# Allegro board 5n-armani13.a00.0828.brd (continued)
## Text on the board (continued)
Ref Des/Silkscreen Bottom: BOT | 2ND | 2'ND
TOP: list("[Spacing] TOP" "24.Shape to Route Keepin" "0 MIL [DEFAULT]" "0 MIL" "0.00 MIL" "DRC ERROR CLASS/TOP" "[Shape] Route Keepin/All ((-191.01 273.9) (8699.38 4792.96))" "[Top Shape] GND ((-190.82 3249.2) (202.99 3569.85))" list(-170.750000 3410.250000) nil)@@@list("iris_chen" "2017/08/22 17:12:43" nil "P16C000357-PC" "5n-armani13.a00")@@@list("anson_lee" "2017/08/24 14:21:02" nil "P172000029-PC" "5n-armani13.a00.0824") | list("[Physical] TOP" "234.Pad/Pad Direct Connect" "NOT_ALLOWED [(GND_20)]" "ALL_ALLOWED" "" "DRC ERROR CLASS/TOP" "[ThruPin] GND (<uTiL>cId2539<uTiL>.6) (-146.76 2401.5)" "[SmdPin] GND (<uTiL>cId2539<uTiL>.5) (-146.76 2401.5)" list(-146.760000 2401.500000) nil)@@@list("iris_chen" "2017/08/23 17:49:26" nil "P16C000357-PC" "5n-armani13.a00")@@@list("anson_lee" "2017/08/24 14:24:34" nil "P172000029-PC" "5n-armani13.a00.0824") | list("[Spacing] TOP" "15.Shape to Route Keepout" "0 MIL [DEFAULT]" "0 MIL" "0.00 MIL" "DRC ERROR CLASS/TOP" "[Shape] Route Keepout/Top ((-101.81 3966.17) (122.4 4195.17))" "[Top Shape] GND ((-191.0 273.91) (8699.37 4792.95))" list(-100.230000 3966.170000) nil)@@@list("iris_chen" "2017/08/22 17:12:55" nil "P16C000357-PC" "5n-armani13.a00")@@@list("anson_lee" "2017/08/24 14:20:44" nil "P172000029-PC" "5n-armani13.a00.0824") | list("[Spacing] TOP" "4.Shape to Route Keepin" "0 MIL [DEFAULT]" "0 MIL" "0.00 MIL" "DRC ERROR CLASS/TOP" "[Shape] Route Keepin/All ((-191.01 273.9) (8699.38 4792.96))" "[Top Shape] GND ((-91.81 3976.17) (117.19 4185.17))" list(-85.450000 3976.170000) nil)@@@list("iris_chen" "2017/08/22 17:12:50" nil "P16C000357-PC" "5n-armani13.a00")@@@list("anson_lee" "2017/08/24 14:08:54" nil "P172000029-PC" "5n-armani13.a00.0824") | list("[Spacing] TOP" "14.Shape to Route Keepin" "0 MIL [DEFAULT]" "0 MIL" "0.00 MIL" "DRC ERROR CLASS/TOP" "[Shape] Route Keepin/All ((-191.01 273.9) (8699.38 4792.96))" "[Top Shape] GND ((-191.0 273.91) (8699.37 4792.95))" list(-27.850000 3902.370000) nil)@@@list("iris_chen" "2017/08/22 17:12:54" nil "P16C000357-PC" "5n-armani13.a00")@@@list("anson_lee" "2017/08/24 14:20:43" nil "P172000029-PC" "5n-armani13.a00.0824") | list("[Spacing] TOP" "9.Shape to Route Keepout" "0 MIL [DEFAULT]" "0 MIL" "0.00 MIL" "DRC ERROR CLASS/TOP" "[Shape] Route Keepout/All ((-211.01 253.9) (8719.38 4812.96))" "[Top Shape] GND ((-24.57 3163.49) (207.43 3395.49))" list(-24.570000 3185.200000) nil)@@@list("iris_chen" "2017/08/22 17:12:52" nil "P16C000357-PC" "5n-armani13.a00")@@@list("anson_lee" "2017/08/24 14:08:59" nil "P172000029-PC" "5n-armani13.a00.0824") | list("[Spacing] TOP" "10.Shape to Route Keepout" "0 MIL [DEFAULT]" "0 MIL" "0.00 MIL" "DRC ERROR CLASS/TOP" "[Shape] Route Keepout/All ((-237.5 2495.83) (182.17 3240.31))" "[Top Shape] GND ((-24.57 3163.49) (207.43 3395.49))" list(-24.570000 3185.190000) nil)@@@list("iris_chen" "2017/08/22 17:12:52" nil "P16C000357-PC" "5n-armani13.a00")@@@list("anson_lee" "2017/08/24 14:09:00" nil "P172000029-PC" "5n-armani13.a00.0824") | list("[Spacing] TOP" "33.Thru Pin to Thru Pin" "5 MIL [(12)]" "4 MIL" "1.00 MIL" "DRC ERROR CLASS/TOP" "[ThruPin] TX2N_P1_C (<uTiL>cId4355<uTiL>.B3) (12.89 3746.02)" "[ThruPin] TX2P_P1_C (<uTiL>cId4355<uTiL>.B2) (12.89 3777.52)" list(12.890000 3759.770000) nil)@@@list("iris_chen" "2017/08/22 17:12:58" nil "P16C000357-PC" "5n-armani13.a00")@@@list("anson_lee" "2017/08/24 14:21:11" nil "P172000029-PC" "5n-armani13.a00.0824") | list("[Spacing] TOP" "17.Thru Pin to Thru Pin" "5 MIL [(12)]" "4 MIL" "1.00 MIL" "DRC ERROR CLASS/TOP" "[ThruPin] RX1N_P1 (<uTiL>cId4355<uTiL>.B10) (12.89 3612.16)" "[ThruPin] RX1P_P1 (<uTiL>cId4355<uTiL>.B11) (12.89 3580.66)" list(12.890000 3598.410000) nil)@@@list("iris_chen" "2017/08/22 17:12:47" nil "P16C000357-PC" "5n-armani13.a00")@@@list("anson_lee" "2017/08/24 14:20:53" nil "P172000029-PC" "5n-armani13.a00.0824") | list("[Spacing] TOP" "27.Shape to Route Keepin" "0 MIL [DEFAULT]" "0 MIL" "0.00 MIL" "DRC ERROR CLASS/TOP" "[Shape] Route Keepin/All ((-191.01 273.9) (8699.38 4792.96))" "[Top Shape] GND ((8.28 3791.73) (47.94 3896.23))" list(17.500000 3892.960000) nil)@@@list("iris_chen" "2017/08/22 17:12:53" nil "P16C000357-PC" "5n-armani13.a00")@@@list("anson_lee" "2017/08/24 14:21:05" nil "P172000029-PC" "5n-armani13.a00.0824") | list("[Spacing] TOP" "30.Thru Pin to Thru Pin" "5 MIL [(15)]" "4 MIL" "1.00 MIL" "DRC ERROR CLASS/TOP" "[ThruPin] DN2 (<uTiL>cId4355<uTiL>.B7) (48.32 3663.34)" "[ThruPin] DP2 (<uTiL>cId4355<uTiL>.B6) (48.32 3694.84)" list(48.320000 3677.090000) nil)@@@list("iris_chen" "2017/08/22 17:12:51" nil "P16C000357-PC" "5n-armani13.a00")@@@list("anson_lee" "2017/08/24 14:21:08" nil "P172000029-PC" "5n-armani13.a00.0824") | list("[Spacing] TOP" "12.Shape to Route Keepout" "0 MIL [DEFAULT]" "0 MIL" "0.00 MIL" "DRC ERROR CLASS/TOP" "[Shape] Route Keepout/Top ((-61.0 1381.68) (193.96 1653.68))" "[Top Shape] GND ((-82.35 352.64) (8095.0 1709.99))" list(183.940000 1648.680000) nil)@@@list("iris_chen" "2017/08/23 18:07:48" nil "P16C000357-PC" "5n-armani13.a00")@@@list("anson_lee" "2017/08/24 14:09:02" nil "P172000029-PC" "5n-armani13.a00.0824") | list("[Spacing] TOP" "1.Shape to Route Keepout" "0 MIL [DEFAULT]" "0 MIL" "0.00 MIL" "DRC ERROR CLASS/TOP" "[Shape] Route Keepout/Top ((-61.0 1381.68) (193.96 1653.68))" "[Top Shape] GND ((-68.02 1359.42) (183.94 1396.0))" list(183.940000 1381.680000) nil)@@@list("iris_chen" "2017/08/23 18:07:47" nil "P16C000357-PC" "5n-armani13.a00")@@@nil | list("[Spacing] TOP" "13.Shape to Route Keepout" "0 MIL [DEFAULT]" "0 MIL" "0.00 MIL" "DRC ERROR CLASS/TOP" "[Shape] Route Keepout/Top ((-61.0 1381.68) (193.96 1653.68))" "[Top Shape] GND ((-68.02 1364.0) (183.94 1396.0))" list(183.940000 1381.680000) nil)@@@list("iris_chen" "2017/08/24 08:51:33" nil "P16C000357-PC" "5n-armani13.a00")@@@list("anson_lee" "2017/08/24 14:09:04" nil "P172000029-PC" "5n-armani13.a00.0824") | list("[Spacing] TOP" "8.Shape to Route Keepin" "0 MIL [DEFAULT]" "0 MIL" "0.00 MIL" "DRC ERROR CLASS/TOP" "[Shape] Route Keepin/All ((-191.01 273.9) (8699.38 4792.96))" "[Top Shape] GND ((-24.57 3163.49) (207.43 3395.49))" list(188.890000 3163.490000) nil)@@@list("iris_chen" "2017/08/22 17:12:51" nil "P16C000357-PC" "5n-armani13.a00")@@@list("anson_lee" "2017/08/24 14:08:58" nil "P172000029-PC" "5n-armani13.a00.0824") | list("[Spacing] TOP" "18.Shape to Route Keepin" "0 MIL [DEFAULT]" "0 MIL" "0.00 MIL" "DRC ERROR CLASS/TOP" "[Shape] Route Keepin/All ((-191.01 273.9) (8699.38 4792.96))" "[Top Shape] GND ((-104.24 2487.0) (342.67 2651.0))" list(189.550000 2589.570000) nil)@@@list("iris_chen" "2017/08/22 17:12:38" nil "P16C000357-PC" "5n-armani13.a00")@@@list("anson_lee" "2017/08/24 14:20:55" nil "P172000029-PC" "5n-armani13.a00.0824") | list("[Physical] TOP" "210.Pad/Pad Direct Connect" "NOT_ALLOWED [85OHM(DP_4|4.3|4|5/4/5/200)]" "ALL_ALLOWED" "" "DRC ERROR CLASS/TOP" "[SmdPin] DP2 (<uTiL>cId4352<uTiL>.4) (300.0 3741.0)" "[SmdPin] DP2 (<uTiL>cId4354<uTiL>.3) (291.47 3739.83)" list(291.470000 3739.830000) nil)@@@list("iris_chen" "2017/08/22 17:19:08" nil "P16C000357-PC" "5n-armani13.a00")@@@list("anson_lee" "2017/08/24 14:24:14" nil "P172000029-PC" "5n-armani13.a00.0824") | list("[Physical] TOP" "206.Pad/Pad Direct Connect" "NOT_ALLOWED [85OHM(DP_4|4.3|4|5/4/5/200)]" "ALL_ALLOWED" "" "DRC ERROR CLASS/TOP" "[SmdPin] DN2 (<uTiL>cId4354<uTiL>.2) (291.47 3718.17)" "[SmdPin] DN2 (<uTiL>cId4352<uTiL>.2) (300.0 3717.0)" list(300.000000 3717.000000) nil)@@@list("iris_chen" "2017/08/22 17:18:53" nil "P16C000357-PC" "5n-armani13.a00")@@@list("anson_lee" "2017/08/24 14:24:11" nil "P172000029-PC" "5n-armani13.a00.0824") | list("[Physical] TOP" "220.Pad/Pad Direct Connect" "NOT_ALLOWED [85OHM(DP_4|4.3|4|5/4/5/200)]" "ALL_ALLOWED" "" "DRC ERROR CLASS/TOP" "[SmdPin] DP2_MUX (<uTiL>cId4354<uTiL>.4) (350.53 3739.83)" "[SmdPin] DP2_MUX (<uTiL>cId4352<uTiL>.3) (342.0 3741.0)" list(342.000000 3741.000000) nil)@@@list("iris_chen" "2017/08/22 17:18:50" nil "P16C000357-PC" "5n-armani13.a00")@@@list("anson_lee" "2017/08/24 14:24:22" nil "P172000029-PC" "5n-armani13.a00.0824") | list("[Physical] TOP" "211.Pad/Pad Direct Connect" "NOT_ALLOWED [85OHM(DP_4|4.3|4|5/4/5/200)]" "ALL_ALLOWED" "" "DRC ERROR CLASS/TOP" "[SmdPin] DN2_MUX (<uTiL>cId4352<uTiL>.1) (342.0 3717.0)" "[SmdPin] DN2_MUX (<uTiL>cId4354<uTiL>.1) (350.53 3718.17)" list(350.530000 3718.170000) nil)@@@list("iris_chen" "2017/08/22 17:19:07" nil "P16C000357-PC" "5n-armani13.a00")@@@list("anson_lee" "2017/08/24 14:24:15" nil "P172000029-PC" "5n-armani13.a00.0824") | list("[Physical] TOP" "204.Pad/Pad Direct Connect" "NOT_ALLOWED [100OHM(DP_#1/#2/5/200)]" "ALL_ALLOWED" "" "DRC ERROR CLASS/TOP" "[SmdPin] RX2N_P1 (<uTiL>cId5011<uTiL>.1) (452.0 3365.0)" "[SmdPin] RX2N_P1 (<uTiL>cId5017<uTiL>.1) (443.47 3364.83)" list(443.470000 3364.830000) nil)@@@list("iris_chen" "2017/08/22 17:19:06" nil "P16C000357-PC" "5n-armani13.a00")@@@list("anson_lee" "2017/08/24 14:24:10" nil "P172000029-PC" "5n-armani13.a00.0824") | list("[Physical] TOP" "208.Pad/Pad Direct Connect" "NOT_ALLOWED [100OHM(DP_#1/#2/5/200)]" "ALL_ALLOWED" "" "DRC ERROR CLASS/TOP" "[SmdPin] RX2P_P1 (<uTiL>cId5017<uTiL>.4) (443.47 3343.17)" "[SmdPin] RX2P_P1 (<uTiL>cId5011<uTiL>.3) (452.0 3341.0)" list(452.000000 3341.000000) nil)@@@list("iris_chen" "2017/08/22 17:18:58" nil "P16C000357-PC" "5n-armani13.a00")@@@list("anson_lee" "2017/08/24 14:24:13" nil "P172000029-PC" "5n-armani13.a00.0824") | list("[Physical] TOP" "245.Pad/Pad Direct Connect" "NOT_ALLOWED [100OHM(DP_#1/#2/5/200)]" "ALL_ALLOWED" "" "DRC ERROR CLASS/TOP" "[SmdPin] RX1P_P1 (<uTiL>cId5012<uTiL>.1) (470.0 3631.0)" "[SmdPin] RX1P_P1 (<uTiL>cId5018<uTiL>.1) (461.47 3629.83)" list(461.470000 3629.830000) nil)@@@list("iris_chen" "2017/08/22 17:18:57" nil "P16C000357-PC" "5n-armani13.a00")@@@list("anson_lee" "2017/08/24 14:24:41" nil "P172000029-PC" "5n-armani13.a00.0824") | list("[Physical] TOP" "221.Pad/Pad Direct Connect" "NOT_ALLOWED [100OHM(DP_#1/#2/5/200)]" "ALL_ALLOWED" "" "DRC ERROR CLASS/TOP" "[SmdPin] RX1N_P1 (<uTiL>cId5018<uTiL>.4) (461.47 3608.17)" "[SmdPin] RX1N_P1 (<uTiL>cId5012<uTiL>.3) (470.0 3607.0)" list(470.000000 3607.000000) nil)@@@list("iris_chen" "2017/08/22 17:19:03" nil "P16C000357-PC" "5n-armani13.a00")@@@list("anson_lee" "2017/08/24 14:24:23" nil "P172000029-PC" "5n-armani13.a00.0824") | list("[Physical] TOP" "222.Pad/Pad Direct Connect" "NOT_ALLOWED [100OHM(DP_#1/#2/5/200)]" "ALL_ALLOWED" "" "DRC ERROR CLASS/TOP" "[SmdPin] TX1P_P1 (<uTiL>cId5010<uTiL>.1) (488.0 3547.0)" "[SmdPin] TX1P_P1 (<uTiL>cId5016<uTiL>.1) (479.47 3545.83)" list(479.470000 3545.830000) nil)@@@list("iris_chen" "2017/08/22 17:18:52" nil "P16C000357-PC" "5n-armani13.a00")@@@list("anson_lee" "2017/08/24 14:24:24" nil "P172000029-PC" "5n-armani13.a00.0824") | list("[Physical] TOP" "241.Pad/Pad Direct Connect" "NOT_ALLOWED [100OHM(DP_#1/#2/5/200)]" "ALL_ALLOWED" "" "DRC ERROR CLASS/TOP" "[SmdPin] TX1N_P1 (<uTiL>cId5010<uTiL>.3) (488.0 3523.0)" "[SmdPin] TX1N_P1 (<uTiL>cId5016<uTiL>.4) (479.47 3524.17)" list(479.470000 3524.170000) nil)@@@list("iris_chen" "2017/08/22 17:19:04" nil "P16C000357-PC" "5n-armani13.a00")@@@list("anson_lee" "2017/08/24 14:24:39" nil "P172000029-PC" "5n-armani13.a00.0824") | list("[Physical] TOP" "242.Pad/Pad Direct Connect" "NOT_ALLOWED [100OHM(DP_#1/#2/5/200)]" "ALL_ALLOWED" "" "DRC ERROR CLASS/TOP" "[SmdPin] RX2N_P1_MUX (<uTiL>cId5017<uTiL>.2) (502.53 3364.83)" "[SmdPin] RX2N_P1_MUX (<uTiL>cId5011<uTiL>.2) (494.0 3365.0)" list(494.000000 3365.000000) nil)@@@list("iris_chen" "2017/08/22 17:19:06" nil "P16C000357-PC" "5n-armani13.a00")@@@list("anson_lee" "2017/08/24 14:24:39" nil "P172000029-PC" "5n-armani13.a00.0824") | list("[Physical] TOP" "219.Pad/Pad Direct Connect" "NOT_ALLOWED [100OHM(DP_#1/#2/5/200)]" "ALL_ALLOWED" "" "DRC ERROR CLASS/TOP" "[SmdPin] RX2P_P1_MUX (<uTiL>cId5011<uTiL>.4) (494.0 3341.0)" "[SmdPin] RX2P_P1_MUX (<uTiL>cId5017<uTiL>.3) (502.53 3343.17)" list(502.530000 3343.170000) nil)@@@list("iris_chen" "2017/08/22 17:18:52" nil "P16C000357-PC" "5n-armani13.a00")@@@list("anson_lee" "2017/08/24 14:24:21" nil "P172000029-PC" "5n-armani13.a00.0824") | list("[Physical] TOP" "217.Pad/Pad Direct Connect" "NOT_ALLOWED [100OHM(DP_#1/#2/5/200)]" "ALL_ALLOWED" "" "DRC ERROR CLASS/TOP" "[SmdPin] RX1P_P1_MUX (<uTiL>cId5012<uTiL>.2) (512.0 3631.0)" "[SmdPin] RX1P_P1_MUX (<uTiL>cId5018<uTiL>.2) (520.53 3629.83)" list(520.530000 3629.830000) nil)@@@list("iris_chen" "2017/08/22 17:19:01" nil "P16C000357-PC" "5n-armani13.a00")@@@list("anson_lee" "2017/08/24 14:24:20" nil "P172000029-PC" "5n-armani13.a00.0824") | list("[Physical] TOP" "240.Pad/Pad Direct Connect" "NOT_ALLOWED [100OHM(DP_#1/#2/5/200)]" "ALL_ALLOWED" "" "DRC ERROR CLASS/TOP" "[SmdPin] RX1N_P1_MUX (<uTiL>cId5012<uTiL>.4) (512.0 3607.0)" "[SmdPin] RX1N_P1_MUX (<uTiL>cId5018<uTiL>.3) (520.53 3608.17)" list(520.530000 3608.170000) nil)@@@list("iris_chen" "2017/08/22 17:18:53" nil "P16C000357-PC" "5n-armani13.a00")@@@list("anson_lee" "2017/08/24 14:24:38" nil "P172000029-PC" "5n-armani13.a00.0824") | list("[Physical] TOP" "207.Pad/Pad Direct Connect" "NOT_ALLOWED [100OHM(DP_#1/#2/5/200)]" "ALL_ALLOWED" "" "DRC ERROR CLASS/TOP" "[SmdPin] TX1N_P1_MUX (<uTiL>cId5016<uTiL>.3) (538.53 3524.17)" "[SmdPin] TX1N_P1_MUX (<uTiL>cId5010<uTiL>.4) (530.0 3523.0)" list(530.000000 3523.000000) nil)@@@list("iris_chen" "2017/08/22 17:19:10" nil "P16C000357-PC" "5n-armani13.a00")@@@list("anson_lee" "2017/08/24 14:24:12" nil "P172000029-PC" "5n-armani13.a00.0824") | list("[Physical] TOP" "218.Pad/Pad Direct Connect" "NOT_ALLOWED [100OHM(DP_#1/#2/5/200)]" "ALL_ALLOWED" "" "DRC ERROR CLASS/TOP" "[SmdPin] TX1P_P1_MUX (<uTiL>cId5010<uTiL>.2) (530.0 3547.0)" "[SmdPin] TX1P_P1_MUX (<uTiL>cId5016<uTiL>.2) (538.53 3545.83)" list(538.530000 3545.830000) nil)@@@list("iris_chen" "2017/08/22 17:19:10" nil "P16C000357-PC" "5n-armani13.a00")@@@list("anson_lee" "2017/08/24 14:24:20" nil "P172000029-PC" "5n-armani13.a00.0824") | list("[Physical] TOP" "216.Pad/Pad Direct Connect" "NOT_ALLOWED [100OHM(DP_#1/#2/5/200)]" "ALL_ALLOWED" "" "DRC ERROR CLASS/TOP" "[SmdPin] TX2P_P1 (<uTiL>cId5009<uTiL>.3) (626.0 3449.0)" "[SmdPin] TX2P_P1 (<uTiL>cId5015<uTiL>.4) (617.47 3450.17)" list(617.470000 3450.170000) nil)@@@list("iris_chen" "2017/08/22 17:19:05" nil "P16C000357-PC" "5n-armani13.a00")@@@list("anson_lee" "2017/08/24 14:24:19" nil "P172000029-PC" "5n-armani13.a00.0824") | list("[Physical] TOP" "243.Pad/Pad Direct Connect" "NOT_ALLOWED [100OHM(DP_#1/#2/5/200)]" "ALL_ALLOWED" "" "DRC ERROR CLASS/TOP" "[SmdPin] TX2N_P1 (<uTiL>cId5015<uTiL>.1) (617.47 3471.83)" "[SmdPin] TX2N_P1 (<uTiL>cId5009<uTiL>.1) (626.0 3473.0)" list(626.000000 3473.000000) nil)@@@list("iris_chen" "2017/08/22 17:19:04" nil "P16C000357-PC" "5n-armani13.a00")@@@list("anson_lee" "2017/08/24 14:24:40" nil "P172000029-PC" "5n-armani13.a00.0824") | list("[Physical] TOP" "223.Pad/Pad Direct Connect" "NOT_ALLOWED [100OHM(DP_#1/#2/5/200)]" "ALL_ALLOWED" "" "DRC ERROR CLASS/TOP" "[SmdPin] TX2N_P1_MUX (<uTiL>cId5009<uTiL>.2) (668.0 3473.0)" "[SmdPin] TX2N_P1_MUX (<uTiL>cId5015<uTiL>.2) (676.53 3471.83)" list(676.530000 3471.830000) nil)@@@list("iris_chen" "2017/08/22 17:19:08" nil "P16C000357-PC" "5n-armani13.a00")@@@list("anson_lee" "2017/08/24 14:24:25" nil "P172000029-PC" "5n-armani13.a00.0824") | list("[Physical] TOP" "205.Pad/Pad Direct Connect" "NOT_ALLOWED [100OHM(DP_#1/#2/5/200)]" "ALL_ALLOWED" "" "DRC ERROR CLASS/TOP" "[SmdPin] TX2P_P1_MUX (<uTiL>cId5009<uTiL>.4) (668.0 3449.0)" "[SmdPin] TX2P_P1_MUX (<uTiL>cId5015<uTiL>.3) (676.53 3450.17)" list(676.530000 3450.170000) nil)@@@list("iris_chen" "2017/08/22 17:18:59" nil "P16C000357-PC" "5n-armani13.a00")@@@list("anson_lee" "2017/08/24 14:24:10" nil "P172000029-PC" "5n-armani13.a00.0824") | list("[Physical] TOP" "202.DiffPair Min Gap" "11.99 MIL [100OHM(DP_#1/#2/5/200)]" "10.19 MIL" "1.80 MIL" "DRC ERROR CLASS/TOP" "[Line] TX2P_P1_MUX ((750.27 3468.26) (770.0 3472.26))" "[Line] TX2N_P1_MUX ((715.37 3479.0) (744.99 3483.0))" list(752.270000 3470.260000) nil)@@@list("iris_chen" "2017/08/22 17:18:58" nil "P16C000357-PC" "5n-armani13.a00")@@@list("anson_lee" "2017/08/24 14:24:08" nil "P172000029-PC" "5n-armani13.a00.0824") | list("[Physical] TOP" "203.DiffPair Min Gap" "11.99 MIL [100OHM(DP_#1/#2/5/200)]" "10.19 MIL" "1.80 MIL" "DRC ERROR CLASS/TOP" "[Line] TX2P_P1_MUX ((745.01 3463.0) (754.27 3472.26))" "[Line] TX2N_P1_MUX ((715.37 3479.0) (744.99 3483.0))" list(752.270000 3470.260000) nil)@@@list("iris_chen" "2017/08/22 17:18:59" nil "P16C000357-PC" "5n-armani13.a00")@@@list("anson_lee" "2017/08/24 14:24:09" nil "P172000029-PC" "5n-armani13.a00.0824") | list("[Physical] TOP" "214.DiffPair Min Gap" "11.99 MIL [100OHM(DP_#1/#2/5/200)]" "10.19 MIL" "1.80 MIL" "DRC ERROR CLASS/TOP" "[Line] TX2P_P1_MUX ((750.27 3468.26) (770.0 3472.26))" "[Line] TX2N_P1_MUX ((740.99 3479.0) (750.0 3488.01))" list(752.270000 3470.260000) nil)@@@list("iris_chen" "2017/08/22 17:18:51" nil "P16C000357-PC" "5n-armani13.a00")@@@list("anson_lee" "2017/08/24 14:24:17" nil "P172000029-PC" "5n-armani13.a00.0824") | list("[Physical] TOP" "215.DiffPair Min Gap" "11.99 MIL [100OHM(DP_#1/#2/5/200)]" "10.19 MIL" "1.80 MIL" "DRC ERROR CLASS/TOP" "[Line] TX2P_P1_MUX ((745.01 3463.0) (754.27 3472.26))" "[Line] TX2N_P1_MUX ((740.99 3479.0) (750.0 3488.01))" list(752.270000 3470.260000) nil)@@@list("iris_chen" "2017/08/22 17:18:51" nil "P16C000357-PC" "5n-armani13.a00")@@@list("anson_lee" "2017/08/24 14:24:17" nil "P172000029-PC" "5n-armani13.a00.0824") | list("[Physical] TOP" "247.DiffPair Min Gap" "11.99 MIL [100OHM(DP_#1/#2/5/200)]" "11.75 MIL" "0.24 MIL" "DRC ERROR CLASS/TOP" "[Line] TX2P_P1_MUX ((745.01 3463.0) (754.27 3472.26))" "[Line] TX2N_P1_MUX ((746.0 3484.01) (770.0 3488.01))" list(752.270000 3470.260000) nil)@@@list("iris_chen" "2017/08/22 17:19:11" nil "P16C000357-PC" "5n-armani13.a00")@@@list("anson_lee" "2017/08/24 14:24:43" nil "P172000029-PC" "5n-armani13.a00.0824") | list("[Physical] TOP" "212.DiffPair Min Gap" "11.99 MIL [100OHM(DP_#1/#2/5/200)]" "11.75 MIL" "0.24 MIL" "DRC ERROR CLASS/TOP" "[Line] TX1N_P1_MUX ((749.0 3513.0) (755.5 3519.5))" "[Line] TX1P_P1_MUX ((744.62 3531.25) (770.0 3535.25))" list(753.500000 3517.500000) nil)@@@list("iris_chen" "2017/08/22 17:19:09" nil "P16C000357-PC" "5n-armani13.a00")@@@list("anson_lee" "2017/08/24 14:24:15" nil "P172000029-PC" "5n-armani13.a00.0824") | list("[Physical] TOP" "246.DiffPair Min Gap" "11.99 MIL [100OHM(DP_#1/#2/5/200)]" "11.75 MIL" "0.24 MIL" "DRC ERROR CLASS/TOP" "[Line] TX2P_P1_MUX ((750.27 3468.26) (770.0 3472.26))" "[Line] TX2N_P1_MUX ((746.0 3484.01) (770.0 3488.01))" list(760.140000 3470.260000) nil)@@@list("iris_chen" "2017/08/22 17:19:11" nil "P16C000357-PC" "5n-armani13.a00")@@@list("anson_lee" "2017/08/24 14:24:42" nil "P172000029-PC" "5n-armani13.a00.0824") | list("[Physical] TOP" "213.DiffPair Min Gap" "11.99 MIL [100OHM(DP_#1/#2/5/200)]" "11.75 MIL" "0.24 MIL" "DRC ERROR CLASS/TOP" "[Line] TX1N_P1_MUX ((751.5 3515.5) (770.0 3519.5))" "[Line] TX1P_P1_MUX ((744.62 3531.25) (770.0 3535.25))" list(760.750000 3517.500000) nil)@@@list("iris_chen" "2017/08/22 17:19:09" nil "P16C000357-PC" "5n-armani13.a00")@@@list("anson_lee" "2017/08/24 14:24:16" nil "P172000029-PC" "5n-armani13.a00.0824") | list("[Physical] TOP" "201.DiffPair Min Gap" "11.99 MIL [100OHM(DP_#1/#2/5/200)]" "11.75 MIL" "0.24 MIL" "DRC ERROR CLASS/TOP" "[Line] RX1N_P1_MUX ((765.75 3562.5) (770.0 3566.75))" "[Line] RX1P_P1_MUX ((694.94 3578.5) (770.0 3582.5))" list(768.000000 3564.750000) nil)@@@list("iris_chen" "2017/08/22 17:18:49" nil "P16C000357-PC" "5n-armani13.a00")@@@list("anson_lee" "2017/08/24 14:24:07" nil "P172000029-PC" "5n-armani13.a00.0824") | list("[Physical] TOP" "209.DiffPair Min Gap" "11.99 MIL [100OHM(DP_#1/#2/5/200)]" "11.74 MIL" "0.25 MIL" "DRC ERROR CLASS/TOP" "[Line] RX2N_P1_MUX ((744.09 3436.76) (770.0 3440.76))" "[Line] RX2P_P1_MUX ((765.74 3420.76) (770.0 3425.02))" list(768.000000 3438.760000) nil)@@@list("iris_chen" "2017/08/22 17:18:50" nil "P16C000357-PC" "5n-armani13.a00")@@@list("anson_lee" "2017/08/24 14:24:13" nil "P172000029-PC" "5n-armani13.a00.0824") | list("[Physical] TOP" "228.Pad/Pad Direct Connect" "NOT_ALLOWED [(GND_20)]" "ALL_ALLOWED" "" "DRC ERROR CLASS/TOP" "[SmdPin] GND (<uTiL>cId4723<uTiL>.41) (840.65 3509.63)" "[ThruPin] GND (<uTiL>cId4723<uTiL>.43) (800.15 3539.16)" list(800.150000 3539.160000) nil)@@@list("iris_chen" "2017/08/22 17:18:54" nil "P16C000357-PC" "5n-armani13.a00")@@@list("anson_lee" "2017/08/24 14:24:28" nil "P172000029-PC" "5n-armani13.a00.0824") | list("[Physical] TOP" "226.Pad/Pad Direct Connect" "NOT_ALLOWED [(GND_20)]" "ALL_ALLOWED" "" "DRC ERROR CLASS/TOP" "[SmdPin] GND (<uTiL>cId4723<uTiL>.41) (840.65 3509.63)" "[ThruPin] GND (<uTiL>cId4723<uTiL>.46) (800.15 3480.1)" list(800.150000 3480.100000) nil)@@@list("iris_chen" "2017/08/22 17:19:00" nil "P16C000357-PC" "5n-armani13.a00")@@@list("anson_lee" "2017/08/24 14:24:27" nil "P172000029-PC" "5n-armani13.a00.0824") | list("[Physical] TOP" "235.Pad/Pad Direct Connect" "NOT_ALLOWED [(GND_20)]" "ALL_ALLOWED" "" "DRC ERROR CLASS/TOP" "[SmdPin] GND (<uTiL>cId4723<uTiL>.41) (840.65 3509.63)" "[ThruPin] GND (<uTiL>cId4723<uTiL>.42) (840.65 3589.58)" list(840.650000 3589.580000) nil)@@@list("iris_chen" "2017/08/22 17:19:07" nil "P16C000357-PC" "5n-armani13.a00")@@@list("anson_lee" "2017/08/24 14:24:35" nil "P172000029-PC" "5n-armani13.a00.0824") | list("[Physical] TOP" "227.Pad/Pad Direct Connect" "NOT_ALLOWED [(GND_20)]" "ALL_ALLOWED" "" "DRC ERROR CLASS/TOP" "[SmdPin] GND (<uTiL>cId4723<uTiL>.41) (840.65 3509.63)" "[ThruPin] GND (<uTiL>cId4723<uTiL>.44) (840.65 3539.16)" list(840.650000 3539.160000) nil)@@@list("iris_chen" "2017/08/22 17:18:54" nil "P16C000357-PC" "5n-armani13.a00")@@@list("anson_lee" "2017/08/24 14:24:28" nil "P172000029-PC" "5n-armani13.a00.0824") | list("[Physical] TOP" "225.Pad/Pad Direct Connect" "NOT_ALLOWED [(GND_20)]" "ALL_ALLOWED" "" "DRC ERROR CLASS/TOP" "[SmdPin] GND (<uTiL>cId4723<uTiL>.41) (840.65 3509.63)" "[ThruPin] GND (<uTiL>cId4723<uTiL>.47) (840.65 3480.1)" list(840.650000 3480.100000) nil)@@@list("iris_chen" "2017/08/22 17:18:56" nil "P16C000357-PC" "5n-armani13.a00")@@@list("anson_lee" "2017/08/24 14:24:26" nil "P172000029-PC" "5n-armani13.a00.0824") | list("[Physical] TOP" "224.Pad/Pad Direct Connect" "NOT_ALLOWED [(GND_20)]" "ALL_ALLOWED" "" "DRC ERROR CLASS/TOP" "[ThruPin] GND (<uTiL>cId4723<uTiL>.49) (840.65 3429.68)" "[SmdPin] GND (<uTiL>cId4723<uTiL>.41) (840.65 3509.63)" list(840.650000 3429.680000) nil)@@@list("iris_chen" "2017/08/22 17:18:53" nil "P16C000357-PC" "5n-armani13.a00")@@@list("anson_lee" "2017/08/24 14:24:25" nil "P172000029-PC" "5n-armani13.a00.0824") | list("[Physical] TOP" "230.Pad/Pad Direct Connect" "NOT_ALLOWED [(GND_20)]" "ALL_ALLOWED" "" "DRC ERROR CLASS/TOP" "[SmdPin] GND (<uTiL>cId4723<uTiL>.41) (840.65 3509.63)" "[ThruPin] GND (<uTiL>cId4723<uTiL>.45) (881.15 3539.16)" list(881.150000 3539.160000) nil)@@@list("iris_chen" "2017/08/22 17:18:55" nil "P16C000357-PC" "5n-armani13.a00")@@@list("anson_lee" "2017/08/24 14:24:31" nil "P172000029-PC" "5n-armani13.a00.0824") | list("[Physical] TOP" "229.Pad/Pad Direct Connect" "NOT_ALLOWED [(GND_20)]" "ALL_ALLOWED" "" "DRC ERROR CLASS/TOP" "[SmdPin] GND (<uTiL>cId4723<uTiL>.41) (840.65 3509.63)" "[ThruPin] GND (<uTiL>cId4723<uTiL>.48) (881.15 3480.1)" list(881.150000 3480.100000) nil)@@@list("iris_chen" "2017/08/22 17:19:03" nil "P16C000357-PC" "5n-armani13.a00")@@@list("anson_lee" "2017/08/24 14:24:29" nil "P172000029-PC" "5n-armani13.a00.0824") | list("[Physical] TOP" "237.Pad/Pad Direct Connect" "NOT_ALLOWED [(GND_20)]" "ALL_ALLOWED" "" "DRC ERROR CLASS/TOP" "[ThruPin] GND (<uTiL>cId18<uTiL>.43) (1300.0 3355.0)" "[SmdPin] GND (<uTiL>cId18<uTiL>.41) (1380.0 3275.0)" list(1300.000000 3355.000000) nil)@@@list("iris_chen" "2017/08/22 17:18:56" nil "P16C000357-PC" "5n-armani13.a00")@@@list("anson_lee" "2017/08/24 14:24:36" nil "P172000029-PC" "5n-armani13.a00.0824") | list("[Physical] TOP" "239.Pad/Pad Direct Connect" "NOT_ALLOWED [(GND_20)]" "ALL_ALLOWED" "" "DRC ERROR CLASS/TOP" "[ThruPin] GND (<uTiL>cId18<uTiL>.42) (1300.0 3195.0)" "[SmdPin] GND (<uTiL>cId18<uTiL>.41) (1380.0 3275.0)" list(1300.000000 3195.000000) nil)@@@list("iris_chen" "2017/08/22 17:18:55" nil "P16C000357-PC" "5n-armani13.a00")@@@list("anson_lee" "2017/08/24 14:24:37" nil "P172000029-PC" "5n-armani13.a00.0824") | list("[Physical] TOP" "236.Pad/Pad Direct Connect" "NOT_ALLOWED [(GND_20)]" "ALL_ALLOWED" "" "DRC ERROR CLASS/TOP" "[ThruPin] GND (<uTiL>cId18<uTiL>.45) (1460.0 3355.0)" "[SmdPin] GND (<uTiL>cId18<uTiL>.41) (1380.0 3275.0)" list(1460.000000 3355.000000) nil)@@@list("iris_chen" "2017/08/22 17:18:57" nil "P16C000357-PC" "5n-armani13.a00")@@@list("anson_lee" "2017/08/24 14:24:35" nil "P172000029-PC" "5n-armani13.a00.0824") | list("[Physical] TOP" "238.Pad/Pad Direct Connect" "NOT_ALLOWED [(GND_20)]" "ALL_ALLOWED" "" "DRC ERROR CLASS/TOP" "[ThruPin] GND (<uTiL>cId18<uTiL>.44) (1460.0 3195.0)" "[SmdPin] GND (<uTiL>cId18<uTiL>.41) (1380.0 3275.0)" list(1460.000000 3195.000000) nil)@@@list("iris_chen" "2017/08/22 17:19:00" nil "P16C000357-PC" "5n-armani13.a00")@@@list("anson_lee" "2017/08/24 14:24:37" nil "P172000029-PC" "5n-armani13.a00.0824") | list("[Spacing] TOP" "1.Shape to Route Keepout" "0 MIL [DEFAULT]" "0 MIL" "0.00 MIL" "DRC ERROR CLASS/TOP" "[Shape] Route Keepout/Top ((3104.74 4379.0) (3459.26 4565.14))" "[Top Shape] GND ((3160.32 4281.45) (3435.92 4557.05))" list(3160.710000 4409.000000) nil)@@@list("iris_chen" "2017/08/22 17:12:42" nil "P16C000357-PC" "5n-armani13.a00")@@@list("anson_lee" "2017/08/24 14:08:48" nil "P172000029-PC" "5n-armani13.a00.0824") | list("[Spacing] TOP" "21.Line to SMD Pin" "4 MIL [[T]=4]" "3.35 MIL" "0.65 MIL" "DRC ERROR CLASS/TOP" "[Line] EMMC_DATA3 ((3620.98 1218.19) (3640.11 1221.19))" "[SmdPin] Dummy (<uTiL>cId4949<uTiL>.B1) (3628.78 1229.54)" list(3628.780000 1219.690000) nil)@@@list("iris_chen" "2017/08/22 17:12:56" nil "P16C000357-PC" "5n-armani13.a00")@@@list("anson_lee" "2017/08/24 14:20:59" nil "P172000029-PC" "5n-armani13.a00.0824") | list("[Spacing] TOP" "23.Line to SMD Pin" "4 MIL [[T]=3.34]" "3.34 MIL" "0.66 MIL" "DRC ERROR CLASS/TOP" "[Line] EMMC_DATA3 ((3620.98 1218.19) (3640.11 1221.19))" "[SmdPin] Dummy (<uTiL>cId4949<uTiL>.C1) (3628.78 1209.85)" list(3628.780000 1219.690000) nil)@@@list("iris_chen" "2017/08/22 17:12:41" nil "P16C000357-PC" "5n-armani13.a00")@@@list("anson_lee" "2017/08/24 14:21:01" nil "P172000029-PC" "5n-armani13.a00.0824") | list("[Spacing] TOP" "22.Line to SMD Pin" "4 MIL [[T]=3.34]" "3.34 MIL" "0.66 MIL" "DRC ERROR CLASS/TOP" "[Line] C0_VDDI ((3617.96 1198.51) (3640.12 1201.51))" "[SmdPin] Dummy (<uTiL>cId4949<uTiL>.C1) (3628.78 1209.85)" list(3628.780000 1200.010000) nil)@@@list("iris_chen" "2017/08/22 17:12:40" nil "P16C000357-PC" "5n-armani13.a00")@@@list("anson_lee" "2017/08/24 14:21:00" nil "P172000029-PC" "5n-armani13.a00.0824") | list("[Spacing] TOP" "29.Line to SMD Pin" "4 MIL [[T]=3.34]" "3.34 MIL" "0.66 MIL" "DRC ERROR CLASS/TOP" "[Line] C0_VDDI ((3617.96 1198.51) (3640.12 1201.51))" "[SmdPin] Dummy (<uTiL>cId4949<uTiL>.D1) (3628.78 1190.17)" list(3628.780000 1200.010000) nil)@@@list("iris_chen" "2017/08/22 17:12:57" nil "P16C000357-PC" "5n-armani13.a00")@@@list("anson_lee" "2017/08/24 14:21:07" nil "P172000029-PC" "5n-armani13.a00.0824") | list("[Spacing] TOP" "16.Line to SMD Pin" "4 MIL [[T]=3.34]" "3.34 MIL" "0.66 MIL" "DRC ERROR CLASS/TOP" "[Line] GND ((3637.12 973.78) (3640.12 1004.66))" "[SmdPin] Dummy (<uTiL>cId4949<uTiL>.P2) (3648.46 993.32)" list(3638.620000 993.320000) nil)@@@list("iris_chen" "2017/08/22 17:12:41" nil "P16C000357-PC" "5n-armani13.a00")@@@list("anson_lee" "2017/08/24 14:20:46" nil "P172000029-PC" "5n-armani13.a00.0824") | list("[Spacing] TOP" "3.Line to SMD Pin" "4 MIL [[T]=3.34]" "3.34 MIL" "0.66 MIL" "DRC ERROR CLASS/TOP" "[Line] GND ((3637.12 973.78) (3640.12 1004.66))" "[SmdPin] Dummy (<uTiL>cId4949<uTiL>.P1) (3628.78 993.32)" list(3638.620000 993.320000) nil)@@@list("iris_chen" "2017/08/22 17:12:50" nil "P16C000357-PC" "5n-armani13.a00")@@@list("anson_lee" "2017/08/24 14:08:52" nil "P172000029-PC" "5n-armani13.a00.0824") | list("[Spacing] TOP" "2.Line to SMD Pin" "4 MIL [[T]=4]" "3.35 MIL" "0.65 MIL" "DRC ERROR CLASS/TOP" "[Line] EMMC_DATA4 ((3656.81 1237.88) (3659.81 1261.19))" "[SmdPin] Dummy (<uTiL>cId4949<uTiL>.A2) (3648.46 1249.22)" list(3658.310000 1249.220000) nil)@@@list("iris_chen" "2017/08/22 17:12:37" nil "P16C000357-PC" "5n-armani13.a00")@@@list("anson_lee" "2017/08/24 14:08:50" nil "P172000029-PC" "5n-armani13.a00.0824") | list("[Spacing] TOP" "20.Line to SMD Pin" "4 MIL [[T]=4]" "3.34 MIL" "0.66 MIL" "DRC ERROR CLASS/TOP" "[Line] EMMC_DATA4 ((3656.81 1237.88) (3659.81 1261.19))" "[SmdPin] EMMC_DATA0 (<uTiL>cId4949<uTiL>.A3) (3668.15 1249.22)" list(3658.310000 1249.220000) nil)@@@list("iris_chen" "2017/08/22 17:12:39" nil "P16C000357-PC" "5n-armani13.a00")@@@list("anson_lee" "2017/08/24 14:20:58" nil "P172000029-PC" "5n-armani13.a00.0824") | list("[Spacing] TOP" "19.Line to SMD Pin" "4 MIL [[T]=4]" "3.34 MIL" "0.66 MIL" "DRC ERROR CLASS/TOP" "[Line] EMMC_DATA5 ((3676.49 1237.88) (3679.49 1262.99))" "[SmdPin] EMMC_DATA0 (<uTiL>cId4949<uTiL>.A3) (3668.15 1249.22)" list(3677.990000 1249.220000) nil)@@@list("iris_chen" "2017/08/22 17:12:39" nil "P16C000357-PC" "5n-armani13.a00")@@@list("anson_lee" "2017/08/24 14:20:57" nil "P172000029-PC" "5n-armani13.a00.0824") | list("[Spacing] TOP" "25.Line to SMD Pin" "4 MIL [[T]=4]" "3.34 MIL" "0.66 MIL" "DRC ERROR CLASS/TOP" "[Line] EMMC_DATA5 ((3676.49 1237.88) (3679.49 1262.99))" "[SmdPin] EMMC_DATA1 (<uTiL>cId4949<uTiL>.A4) (3687.83 1249.22)" list(3677.990000 1249.220000) nil)@@@list("iris_chen" "2017/08/22 17:12:44" nil "P16C000357-PC" "5n-armani13.a00")@@@list("anson_lee" "2017/08/24 14:21:03" nil "P172000029-PC" "5n-armani13.a00.0824") | list("[Spacing] TOP" "26.Line to SMD Pin" "4 MIL [[T]=4]" "3.34 MIL" "0.66 MIL" "DRC ERROR CLASS/TOP" "[Line] EMMC_DATA6 ((3696.17 1237.89) (3699.17 1263.09))" "[SmdPin] EMMC_DATA1 (<uTiL>cId4949<uTiL>.A4) (3687.83 1249.22)" list(3697.670000 1249.220000) nil)@@@list("iris_chen" "2017/08/22 17:12:45" nil "P16C000357-PC" "5n-armani13.a00")@@@list("anson_lee" "2017/08/24 14:21:04" nil "P172000029-PC" "5n-armani13.a00.0824") | list("[Spacing] TOP" "31.Line to SMD Pin" "4 MIL [[T]=4]" "3.35 MIL" "0.65 MIL" "DRC ERROR CLASS/TOP" "[Line] EMMC_DATA6 ((3696.17 1237.89) (3699.17 1263.09))" "[SmdPin] EMMC_DATA2 (<uTiL>cId4949<uTiL>.A5) (3707.52 1249.22)" list(3697.670000 1249.220000) nil)@@@list("iris_chen" "2017/08/22 17:12:46" nil "P16C000357-PC" "5n-armani13.a00")@@@list("anson_lee" "2017/08/24 14:21:09" nil "P172000029-PC" "5n-armani13.a00.0824") | list("[Spacing] TOP" "28.Line to SMD Pin" "4 MIL [[T]=4]" "3.26 MIL" "0.74 MIL" "DRC ERROR CLASS/TOP" "[Line] EMMC_DATA7 ((3715.94 1237.8) (3718.94 1263.45))" "[SmdPin] GND (<uTiL>cId4949<uTiL>.A6) (3727.2 1249.22)" list(3717.440000 1249.220000) nil)@@@list("iris_chen" "2017/08/22 17:12:56" nil "P16C000357-PC" "5n-armani13.a00")@@@list("anson_lee" "2017/08/24 14:21:06" nil "P172000029-PC" "5n-armani13.a00.0824") | list("[Spacing] TOP" "32.Line to SMD Pin" "4 MIL [[T]=4]" "3.42 MIL" "0.58 MIL" "DRC ERROR CLASS/TOP" "[Line] EMMC_DATA7 ((3715.94 1237.8) (3718.94 1263.45))" "[SmdPin] EMMC_DATA2 (<uTiL>cId4949<uTiL>.A5) (3707.52 1249.22)" list(3717.440000 1249.220000) nil)@@@list("iris_chen" "2017/08/22 17:12:46" nil "P16C000357-PC" "5n-armani13.a00")@@@list("anson_lee" "2017/08/24 14:21:10" nil "P172000029-PC" "5n-armani13.a00.0824") | list("[Physical] TOP" "233.Pad/Pad Direct Connect" "NOT_ALLOWED [(GND_20)]" "ALL_ALLOWED" "" "DRC ERROR CLASS/TOP" "[SmdPin] GND (<uTiL>cId4917<uTiL>.21) (3745.0 4105.0)" "[ThruPin] GND (<uTiL>cId4917<uTiL>.22) (3724.5 4125.5)" list(3724.500000 4125.500000) nil)@@@list("iris_chen" "2017/08/22 17:19:01" nil "P16C000357-PC" "5n-armani13.a00")@@@list("anson_lee" "2017/08/24 14:24:33" nil "P172000029-PC" "5n-armani13.a00.0824") | list("[Physical] TOP" "244.Pad/Pad Direct Connect" "NOT_ALLOWED [(GND_20)]" "ALL_ALLOWED" "" "DRC ERROR CLASS/TOP" "[SmdPin] GND (<uTiL>cId4917<uTiL>.21) (3745.0 4105.0)" "[ThruPin] GND (<uTiL>cId4917<uTiL>.24) (3724.5 4084.5)" list(3724.500000 4084.500000) nil)@@@list("iris_chen" "2017/08/22 17:19:02" nil "P16C000357-PC" "5n-armani13.a00")@@@list("anson_lee" "2017/08/24 14:24:41" nil "P172000029-PC" "5n-armani13.a00.0824") | list("[Physical] TOP" "232.Pad/Pad Direct Connect" "NOT_ALLOWED [(GND_20)]" "ALL_ALLOWED" "" "DRC ERROR CLASS/TOP" "[SmdPin] GND (<uTiL>cId4917<uTiL>.21) (3745.0 4105.0)" "[ThruPin] GND (<uTiL>cId4917<uTiL>.23) (3765.5 4125.5)" list(3765.500000 4125.500000) nil)@@@list("iris_chen" "2017/08/22 17:19:02" nil "P16C000357-PC" "5n-armani13.a00")@@@list("anson_lee" "2017/08/24 14:24:32" nil "P172000029-PC" "5n-armani13.a00.0824") | list("[Physical] TOP" "231.Pad/Pad Direct Connect" "NOT_ALLOWED [(GND_20)]" "ALL_ALLOWED" "" "DRC ERROR CLASS/TOP" "[ThruPin] GND (<uTiL>cId4917<uTiL>.25) (3765.5 4084.5)" "[SmdPin] GND (<uTiL>cId4917<uTiL>.21) (3745.0 4105.0)" list(3765.500000 4084.500000) nil)@@@list("iris_chen" "2017/08/22 17:19:05" nil "P16C000357-PC" "5n-armani13.a00")@@@list("anson_lee" "2017/08/24 14:24:32" nil "P172000029-PC" "5n-armani13.a00.0824") | list("[Spacing] TOP" "11.Shape to Route Keepin" "0 MIL [DEFAULT]" "0 MIL" "0.00 MIL" "DRC ERROR CLASS/TOP" "[Shape] Route Keepin/All ((-191.01 273.9) (8699.38 4792.96))" "[Top Shape] GND ((-82.35 352.64) (8095.0 1709.99))" list(3884.420000 504.590000) nil)@@@list("iris_chen" "2017/08/22 17:12:44" nil "P16C000357-PC" "5n-armani13.a00")@@@list("anson_lee" "2017/08/24 14:09:01" nil "P172000029-PC" "5n-armani13.a00.0824") | list("[Spacing] TOP" "6.Shape to Route Keepout" "0 MIL [DEFAULT]" "0 MIL" "0.00 MIL" "DRC ERROR CLASS/TOP" "[Shape] Route Keepout/All ((-211.01 253.9) (8719.38 4812.96))" "[Top Shape] GND ((7845.35 627.0) (8160.35 935.02))" list(7937.730000 634.110000) nil)@@@list("iris_chen" "2017/08/22 17:12:48" nil "P16C000357-PC" "5n-armani13.a00")@@@list("anson_lee" "2017/08/24 14:08:56" nil "P172000029-PC" "5n-armani13.a00.0824") | list("[Spacing] TOP" "7.Shape to Route Keepin" "0 MIL [DEFAULT]" "0 MIL" "0.00 MIL" "DRC ERROR CLASS/TOP" "[Shape] Route Keepin/All ((-191.01 273.9) (8699.38 4792.96))" "[Top Shape] GND ((7845.35 627.0) (8160.35 935.02))" list(8061.030000 631.160000) nil)@@@list("iris_chen" "2017/08/22 17:12:49" nil "P16C000357-PC" "5n-armani13.a00")@@@list("anson_lee" "2017/08/24 14:08:57" nil "P172000029-PC" "5n-armani13.a00.0824") | list("[Spacing] TOP" "5.Shape to Route Keepin" "0 MIL [DEFAULT]" "0 MIL" "0.00 MIL" "DRC ERROR CLASS/TOP" "[Shape] Route Keepin/All ((-191.01 273.9) (8699.38 4792.96))" "[Top Shape] GND ((8073.6 273.9) (8493.57 637.37))" list(8084.820000 619.960000) nil)@@@list("iris_chen" "2017/08/22 17:12:48" nil "P16C000357-PC" "5n-armani13.a00")@@@list("anson_lee" "2017/08/24 14:08:55" nil "P172000029-PC" "5n-armani13.a00.0824")
Ref Des/Silkscreen Top: TOP | 1ST | ARMANI13 MAIN BOARD | PCB MADE IN | REV:A00 | PCB BARCODE | 1'ST
GND1: list("[Spacing] GND1" "33.Shape to Route Keepin" "0 MIL [DEFAULT]" "0 MIL" "0.00 MIL" "DRC ERROR CLASS/GND1" "[Shape] Route Keepin/All ((-191.01 273.9) (8699.38 4792.96))" "[Gnd1 Shape] GND ((-191.01 273.9) (8699.38 4792.96))" list(-156.360000 2335.000000) nil)@@@list("iris_chen" "2017/08/22 17:12:59" nil "P16C000357-PC" "5n-armani13.a00")@@@nil | list("[Spacing] GND1" "35.Shape to Route Keepin" "0 MIL [DEFAULT]" "0 MIL" "0.00 MIL" "DRC ERROR CLASS/GND1" "[Shape] Route Keepin/All ((-191.01 273.9) (8699.38 4792.96))" "[Gnd1 Shape] AGND ((-137.46 1141.0) (434.0 2428.0))" list(-129.620000 2286.830000) nil)@@@list("iris_chen" "2017/08/22 17:12:58" nil "P16C000357-PC" "5n-armani13.a00")@@@list("anson_lee" "2017/08/24 14:21:14" nil "P172000029-PC" "5n-armani13.a00.0824") | list("[Spacing-SameNet] GND1" "187.Thru Pin to Shape Same Net" "5 MIL [DEFAULT]" "0 MIL" "5.00 MIL" "DRC ERROR CLASS/GND1" "[ThruPin] GND (<uTiL>cId30<uTiL>.51) (380.5 1405.0)" "[Gnd1 Shape] GND ((-191.01 273.9) (8699.38 4792.96))" list(381.000000 1416.990000) nil)@@@list("iris_chen" "2017/08/22 17:18:42" nil "P16C000357-PC" "5n-armani13.a00")@@@list("anson_lee" "2017/08/24 14:23:57" nil "P172000029-PC" "5n-armani13.a00.0824") | list("[Spacing-SameNet] GND1" "186.Thru Pin to Shape Same Net" "5 MIL [DEFAULT]" "0 MIL" "5.00 MIL" "DRC ERROR CLASS/GND1" "[ThruPin] GND (<uTiL>cId30<uTiL>.52) (380.5 1325.5)" "[Gnd1 Shape] GND ((-191.01 273.9) (8699.38 4792.96))" list(381.000000 1337.490000) nil)@@@list("iris_chen" "2017/08/22 17:18:42" nil "P16C000357-PC" "5n-armani13.a00")@@@list("anson_lee" "2017/08/24 14:23:56" nil "P172000029-PC" "5n-armani13.a00.0824") | list("[Spacing-SameNet] GND1" "188.Thru Pin to Shape Same Net" "5 MIL [DEFAULT]" "0 MIL" "5.00 MIL" "DRC ERROR CLASS/GND1" "[ThruPin] GND (<uTiL>cId30<uTiL>.50) (380.5 1484.5)" "[Gnd1 Shape] GND ((-191.01 273.9) (8699.38 4792.96))" list(392.490000 1484.000000) nil)@@@list("iris_chen" "2017/08/22 17:18:43" nil "P16C000357-PC" "5n-armani13.a00")@@@list("anson_lee" "2017/08/24 14:23:57" nil "P172000029-PC" "5n-armani13.a00.0824") | list("[Spacing] GND1" "34.Shape to Route Keepin" "0 MIL [DEFAULT]" "0 MIL" "0.00 MIL" "DRC ERROR CLASS/GND1" "[Shape] Route Keepin/All ((-191.01 273.9) (8699.38 4792.96))" "[Gnd1 Shape] GND ((-191.01 273.9) (8699.38 4792.96))" list(3463.780000 4760.350000) nil)@@@list("iris_chen" "2017/08/23 17:49:24" nil "P16C000357-PC" "5n-armani13.a00")@@@list("anson_lee" "2017/08/24 14:21:13" nil "P172000029-PC" "5n-armani13.a00.0824")
IN1: list("[Spacing] IN1" "38.Shape to Route Keepin" "0 MIL [DEFAULT]" "0 MIL" "0.00 MIL" "DRC ERROR CLASS/IN1" "[Shape] Route Keepin/All ((-191.01 273.9) (8699.38 4792.96))" "[In1 Shape] GND ((-178.93 2335.01) (372.0 2675.16))" list(-117.680000 2460.370000) nil)@@@list("iris_chen" "2017/08/22 17:13:00" nil "P16C000357-PC" "5n-armani13.a00")@@@list("anson_lee" "2017/08/24 14:21:17" nil "P172000029-PC" "5n-armani13.a00.0824") | list("[Spacing] IN1" "37.Shape to Route Keepin" "0 MIL [DEFAULT]" "0 MIL" "0.00 MIL" "DRC ERROR CLASS/IN1" "[Shape] Route Keepin/All ((-191.01 273.9) (8699.38 4792.96))" "[In1 Shape] AGND ((35.94 2279.8) (163.55 2342.99))" list(35.940000 2279.810000) nil)@@@list("iris_chen" "2017/08/22 17:13:02" nil "P16C000357-PC" "5n-armani13.a00")@@@list("anson_lee" "2017/08/24 14:21:16" nil "P172000029-PC" "5n-armani13.a00.0824") | list("[Spacing] IN1" "40.Shape to Route Keepin" "0 MIL [DEFAULT]" "0 MIL" "0.00 MIL" "DRC ERROR CLASS/IN1" "[Shape] Route Keepin/All ((-191.01 273.9) (8699.38 4792.96))" "[In1 Shape] GND ((-190.82 3060.98) (345.0 3565.78))" list(170.480000 3064.980000) nil)@@@list("iris_chen" "2017/08/22 17:13:00" nil "P16C000357-PC" "5n-armani13.a00")@@@list("anson_lee" "2017/08/24 14:21:19" nil "P172000029-PC" "5n-armani13.a00.0824") | list("[Spacing] IN1" "41.Shape to Route Keepin" "0 MIL [DEFAULT]" "0 MIL" "0.00 MIL" "DRC ERROR CLASS/IN1" "[Shape] Route Keepin/All ((-191.01 273.9) (8699.38 4792.96))" "[In1 Shape] AGND ((-82.35 1141.02) (433.98 2317.5))" list(272.850000 2014.550000) nil)@@@list("iris_chen" "2017/08/22 17:13:03" nil "P16C000357-PC" "5n-armani13.a00")@@@list("anson_lee" "2017/08/24 14:21:20" nil "P172000029-PC" "5n-armani13.a00.0824") | list("[Spacing] IN1" "39.Shape to Route Keepin" "0 MIL [DEFAULT]" "0 MIL" "0.00 MIL" "DRC ERROR CLASS/IN1" "[Shape] Route Keepin/All ((-191.01 273.9) (8699.38 4792.96))" "[In1 Shape] GND ((-82.35 352.64) (7949.09 1709.99))" list(3884.420000 504.590000) nil)@@@list("iris_chen" "2017/08/22 17:13:01" nil "P16C000357-PC" "5n-armani13.a00")@@@list("anson_lee" "2017/08/24 14:21:18" nil "P172000029-PC" "5n-armani13.a00.0824") | list("[Spacing] IN1" "36.Shape to Route Keepin" "0 MIL [DEFAULT]" "0 MIL" "0.00 MIL" "DRC ERROR CLASS/IN1" "[Shape] Route Keepin/All ((-191.01 273.9) (8699.38 4792.96))" "[In1 Shape] GND ((8039.3 273.9) (8493.57 649.68))" list(8126.570000 590.190000) nil)@@@list("iris_chen" "2017/08/22 17:13:02" nil "P16C000357-PC" "5n-armani13.a00")@@@list("anson_lee" "2017/08/24 14:21:15" nil "P172000029-PC" "5n-armani13.a00.0824")
